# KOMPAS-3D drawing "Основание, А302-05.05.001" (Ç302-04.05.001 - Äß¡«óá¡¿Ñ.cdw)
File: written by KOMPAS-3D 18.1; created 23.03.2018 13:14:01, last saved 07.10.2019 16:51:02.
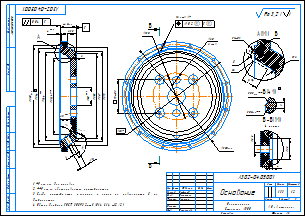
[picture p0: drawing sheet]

Sheet 1: A3, landscape

Document properties: Автор: Милов; Организация: Милов; Полное имя файла: D:\Мембранные насосы\Мембранный электропривод\А302-00.00.000 - ASTRA-302 (МЭ200)\А302-04.00.000 - Мембранный насос ASTRA-302-PP\А302-04.05.001 - Основание.cdw; Параметр неуказанной шероховатости: Ra 3,2; Масса: 1.33492

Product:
- Part/product: Основание  | designation А302-05.05.001
    Материал: Полипропилен  ГОСТ 26996-86 (density 900 kg/m3)
    Масса: 1.33492
    Раздел спецификации: Детали
    Форматы листов документа: A3
    source file: ..\А302-05.00.000 - Мембранный насос ASTRA-302-PVC\А302-05.05.001 - Основание.cdw
- Part/product: Основание  | designation А302-04.05.001
    Материал: Полипропилен  ГОСТ 26996-86 (density 900 kg/m3)
    Масса: 1.33492
    Раздел спецификации: Детали
    Форматы листов документа: A3
    source file: ..\Чертежи ПВХ\А302-02.05.001 - Основание.cdw, ..\Чертежи Полипропилен\А302-03.05.001 - Основание.cdw
- Part/product: Основание  | designation А302-00.05.001
    Материал: Полипропилен  ГОСТ 26996-86 (density 900 kg/m3)
    Масса: 1.33086
    Раздел спецификации: Детали
    Форматы листов документа: A3
    source file: \\192.168.87.28\Konstructor_doc\Мембранные насосы\Мембранный электропривод\А302-00.00.000 - ASTRA-302 (МЭ200)\Чертежи\А302-00.05.001 - Основание.cdw
- Part/product: Основание  | designation А302-03.05.001
    Материал: Полипропилен  ГОСТ 26996-86 (density 900 kg/m3)
    Масса: 1.33086
    Раздел спецификации: Детали
    Форматы листов документа: A3

Title block, sheet 1: Наименование: Основание; designation: А302-04.05.001; Материал: Полипропилен / Стержень  300; Масса: 1,33; scale: 1:2; Количество листов документа: 1; organisation: АО «Астерион»; Форматы листов документа: A3; stored path: \\192.168.87.28\Konstructor_doc\Мембранные насосы\Мембранный электропривод\А302-00.00.000 - ASTRA-302 (МЭ200)\Чертежи\А302-00.05.001 - Основание.cdw; Разработал: Лифлянд; Проверил: Борисенко; Т. контр.: Лучихин; Утвердил: Григорьева

Views: Вид 1, Местный разрез 1, Вид:3, Проекционный вид 2, Выносной элемент 3, Разрез 4, Выносной элемент 5, Выносной элемент А, Выносной элемент, Разрез В-В, Выносной элемент Б
Referenced files in D:\Мембранные насосы\Мембранный электропривод\А302-00.00.000 - ASTRA-302 (МЭ200)\3Д\: А302-00.05.001 - Основание.m3d
Referenced files in Z:\Мембранные насосы\Мембранный электропривод\А302-00.00.000 - ASTRA-302 (МЭ200)\3Д\: А302-00.05.001 - Основание.m3d
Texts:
  Ra 3,2
  Ra 3,2 ( )
Dimensions and other numbers on the sheet: 16; 9; 50; 4; 44,5; 272; 28; 280; 211,67; 244; 0,04; 23,5; 247; 235; 2; 264; 300; 20; 2 отв.; 130; 287; 12 отв.; 7; 92±0,2; 6; 12; 2,5; 15; 1±0,1; 4 места; 8,5; 0,5; 1:2; 1,33

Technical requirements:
  *Размеры для справок.
  **Размер обеспечивается инструментом.
  Следы инструмента, царапины и риски на поверхности Д не
  допускаются.
  Общие допуски ГОСТ 30893.2-mK (H14, h14,  t2/2).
